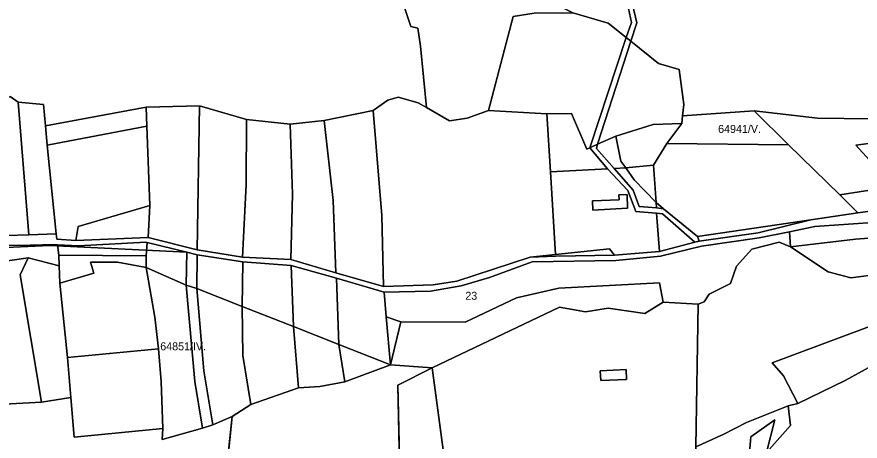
# Model space of a CAD drawing. Extents: x -521261 to -517465, y -1182764 to -1179456.
# Drawn here: x -520761 to -520234, y -1181154 to -1180889 of the extents above; entities that cross this region are included whole.
import ezdxf

# ---------------------------------------------------------------- set-up
doc = ezdxf.new("R2010")
doc.units = 0
for name, color, linetype in [('95610013', 7, 'Continuous'), ('95620013', 7, 'Continuous'), ('95640013', 7, 'Continuous'), ('95660013', 7, 'Continuous')]:
    doc.layers.add(name, color=color, linetype=linetype)

msp = doc.modelspace()

# ---------------------------------------------------------------- linework, layer by layer
at = {"layer": '95610013'}
for points in [[(-520413.63, -1180886.67), (-520391.57, -1180893.1), (-520380.19, -1180902.05), (-520402.93, -1180971), (-520404.76, -1180971.74), (-520414.45, -1180949.49), (-520429.91, -1180949.77), (-520466.27, -1180947.66), (-520450.85, -1180888.84), (-520437.74, -1180886.84)], [(-520377.28, -1180904.27), (-520360, -1180918.29), (-520347.18, -1180922.08), (-520344.3, -1180943.96), (-520344.99, -1180950.96), (-520345.48, -1180955.74), (-520363.32, -1180956.31), (-520386.65, -1180963.6), (-520398.19, -1180968.76)], [(-520765.33, -1180938.81), (-520760.21, -1180942.51), (-520753.55, -1181025.36), (-520781.8, -1181026.11), (-520776.76, -1181017.76), (-520775.73, -1181015.12), (-520782.22, -1180993.52), (-520780.05, -1180973.32), (-520778.12, -1180965.89), (-520770.41, -1180941.78)], [(-520522.77, -1180939.3), (-520510.22, -1180942.87), (-520505.09, -1180945.85), (-520490.67, -1180954.03), (-520479.73, -1180952.5), (-520466.27, -1180947.66), (-520429.91, -1180949.77), (-520427.6, -1180986), (-520424.35, -1181037.58), (-520440.29, -1181039.26), (-520486.21, -1181054.21), (-520500.85, -1181056.65), (-520531.99, -1181057.53), (-520532.9, -1181013.34), (-520538.35, -1180947.59), (-520529.26, -1180941.13)], [(-520744.49, -1180944), (-520743.19, -1180957.3), (-520742.11, -1180969.27), (-520736.5, -1181024.64), (-520753.55, -1181025.36), (-520760.21, -1180942.51)], [(-520646.99, -1180944.71), (-520648.3, -1181034.75), (-520679.07, -1181027.05), (-520678, -1181007.02), (-520679.88, -1180957.43), (-520680.17, -1180945.51)], [(-520617.63, -1180953.24), (-520617.73, -1180993.81), (-520619.96, -1181039.3), (-520648.3, -1181034.75), (-520646.99, -1180944.71)], [(-520538.35, -1180947.59), (-520532.9, -1181013.34), (-520531.99, -1181057.53), (-520561.77, -1181049.02), (-520563.49, -1181003.85), (-520569.05, -1180953.85)], [(-520414.45, -1180949.49), (-520404.76, -1180971.74), (-520402.93, -1180971), (-520391.92, -1180984.05), (-520427.6, -1180986), (-520429.91, -1180949.77)], [(-520300.29, -1180947.88), (-520278.88, -1180969.13), (-520354.95, -1180968.17), (-520345.48, -1180955.74), (-520344.99, -1180950.96)], [(-520260.64, -1180952.48), (-520227.61, -1180952.85), (-520219.04, -1180948.87), (-520200.55, -1180964.48), (-520236.79, -1180969.29), (-520213.15, -1180995.05), (-520246.78, -1181000.33), (-520278.88, -1180969.13), (-520300.29, -1180947.88)], [(-520212.94, -1180946.42), (-520201.71, -1180960.23), (-520187.3, -1180962.26), (-520183.85, -1180959.97), (-520160.25, -1180989.16), (-520140.01, -1181013.64), (-520196.24, -1181010.47), (-520209.39, -1181007.96), (-520235.48, -1181011.57), (-520246.78, -1181000.33), (-520213.15, -1180995.05), (-520236.79, -1180969.29), (-520200.55, -1180964.48), (-520219.04, -1180948.87)], [(-520590.31, -1180956.29), (-520588.89, -1180999.87), (-520589.94, -1181040.83), (-520619.96, -1181039.3), (-520617.73, -1180993.81), (-520617.63, -1180953.24)], [(-520569.05, -1180953.85), (-520563.49, -1181003.85), (-520561.77, -1181049.02), (-520589.94, -1181040.83), (-520588.89, -1180999.87), (-520590.31, -1180956.29)], [(-520363.32, -1180956.31), (-520345.48, -1180955.74), (-520354.95, -1180968.17), (-520363.12, -1180981.91), (-520380.53, -1180983.43), (-520383.57, -1180979.21), (-520386.65, -1180963.6)], [(-520742.11, -1180969.27), (-520679.88, -1180957.43), (-520678, -1181007.02), (-520722.82, -1181020.21), (-520724.29, -1181028.9), (-520736.16, -1181028.06), (-520736.5, -1181024.64)], [(-520398.19, -1180968.76), (-520386.65, -1180963.6), (-520383.57, -1180979.21), (-520380.53, -1180983.43), (-520387.73, -1180983.85), (-520398.77, -1180971.41)], [(-520354.95, -1180968.17), (-520278.88, -1180969.13), (-520246.78, -1181000.33), (-520235.48, -1181011.57), (-520264.93, -1181015.96), (-520335.73, -1181026.42), (-520356.95, -1181009.05), (-520361.63, -1181005.12), (-520363.12, -1180981.91)], [(-520678, -1181007.02), (-520679.07, -1181027.05), (-520724.29, -1181028.9), (-520722.82, -1181020.21)], [(-520361.32, -1181008.5), (-520361.63, -1181005.12), (-520356.95, -1181009.05)], [(-520361.22, -1181011.78), (-520357.66, -1181012.23), (-520337.45, -1181029.91), (-520359.36, -1181035.81)], [(-520390.73, -1181034.03), (-520387.65, -1181038.15), (-520424.28, -1181038.64), (-520440.29, -1181039.26), (-520424.35, -1181037.58)], [(-520754, -1181039.73), (-520758.98, -1181050.37), (-520745.59, -1181130), (-520769.1, -1181131.19), (-520787.16, -1181111.94), (-520795.31, -1181089.15), (-520789.59, -1181054.58), (-520789.95, -1181044.99)], [(-520734.68, -1181044.73), (-520734.18, -1181055.46), (-520729.43, -1181102.02), (-520727.31, -1181126.94), (-520745.59, -1181130), (-520758.98, -1181050.37), (-520754, -1181039.73)], [(-520715.02, -1181042.38), (-520698.14, -1181042.43), (-520680.34, -1181045.76), (-520674.82, -1181076.71), (-520672.52, -1181096.48), (-520729.43, -1181102.02), (-520734.18, -1181055.46), (-520712.92, -1181049.21)], [(-520655.3, -1181056.85), (-520649.82, -1181117.07), (-520645.15, -1181146.15), (-520670.21, -1181153.14), (-520669.91, -1181146.41), (-520670.9, -1181116.98), (-520672.52, -1181096.48), (-520674.82, -1181076.71), (-520680.34, -1181045.76)], [(-520655.3, -1181056.85), (-520648.69, -1181058.96), (-520644.18, -1181110.25), (-520638.52, -1181144.14), (-520645.15, -1181146.15), (-520649.82, -1181117.07)], [(-520620.31, -1181070.08), (-520619.94, -1181100.8), (-520614.85, -1181131.39), (-520626.5, -1181138.86), (-520638.52, -1181144.14), (-520644.18, -1181110.25), (-520648.69, -1181058.96)], [(-520588.28, -1181082.68), (-520585.05, -1181120.87), (-520614.85, -1181131.39), (-520619.94, -1181100.8), (-520620.31, -1181070.08)], [(-520559.83, -1181093.86), (-520556.17, -1181117.12), (-520571.69, -1181120.15), (-520585.05, -1181120.87), (-520588.28, -1181082.68)], [(-520729.43, -1181102.02), (-520672.52, -1181096.48), (-520670.9, -1181116.98), (-520669.91, -1181146.41), (-520725.36, -1181151.77), (-520727.31, -1181126.94)], [(-520527.54, -1181106.61), (-520556.17, -1181117.12), (-520559.83, -1181093.86)], [(-520501.61, -1181108.38), (-520522.92, -1181119.2), (-520521.72, -1181178.92), (-520635.15, -1181227.75), (-520634.86, -1181222.95), (-520634.84, -1181222.55), (-520632.77, -1181200.01), (-520629.67, -1181169.79), (-520626.5, -1181138.86), (-520614.85, -1181131.39), (-520585.05, -1181120.87), (-520571.69, -1181120.15), (-520556.17, -1181117.12), (-520527.54, -1181106.61)]]:
    msp.add_lwpolyline(points, close=True, dxfattribs=at)
at = {"layer": '95620013'}
for points in [[(-520153.4, -1180806.35), (-520157.92, -1180932.93), (-520196.52, -1180926.36), (-520199.57, -1180927.79), (-520202.96, -1180943.49), (-520212.94, -1180946.42), (-520219.04, -1180948.87), (-520227.61, -1180952.85), (-520260.64, -1180952.48), (-520300.29, -1180947.88), (-520344.99, -1180950.96), (-520344.3, -1180943.96), (-520347.18, -1180922.08), (-520360, -1180918.29), (-520377.28, -1180904.27), (-520373.63, -1180892.94), (-520376.27, -1180881.41), (-520440.58, -1180853.57), (-520296.21, -1180829.93)], [(-520447.63, -1180855.08), (-520441.44, -1180872.23), (-520413.63, -1180886.67), (-520437.74, -1180886.84), (-520450.85, -1180888.84), (-520466.27, -1180947.66), (-520479.73, -1180952.5), (-520490.67, -1180954.03), (-520505.09, -1180945.85), (-520508.85, -1180907.38), (-520510.51, -1180896.3), (-520514.96, -1180895.18), (-520522.73, -1180871.37), (-520521.14, -1180864.38), (-520485.24, -1180860)], [(-520441.44, -1180872.23), (-520447.63, -1180855.08), (-520378.72, -1180883.92), (-520376.96, -1180892.63), (-520380.19, -1180902.05), (-520391.57, -1180893.1), (-520413.63, -1180886.67)], [(-520297.08, -1181027.2), (-520278.14, -1181023.43), (-520277.6, -1181032.76), (-520284.69, -1181029.91), (-520301.71, -1181034.37), (-520311.25, -1181044.99), (-520315.05, -1181055.77), (-520328.37, -1181062.33), (-520331.46, -1181067.2), (-520335.2, -1181068.61), (-520357.23, -1181067.33), (-520359.55, -1181055.32), (-520422.46, -1181058.72), (-520448.82, -1181064.74), (-520480.94, -1181079.95), (-520521.06, -1181079.73), (-520530.28, -1181076.6), (-520531.56, -1181061.16), (-520502.66, -1181060.46), (-520483.49, -1181057.27), (-520465.6, -1181051.94), (-520439.04, -1181042.18), (-520386.77, -1181041.34), (-520358.9, -1181038.71), (-520333.23, -1181032.5)], [(-520654.8, -1181036.24), (-520648.35, -1181037.93), (-520648.69, -1181058.96), (-520655.3, -1181056.85)], [(-520648.35, -1181037.93), (-520619.95, -1181042.28), (-520620.31, -1181070.08), (-520648.69, -1181058.96)], [(-520619.95, -1181042.28), (-520589.61, -1181044.45), (-520588.28, -1181082.68), (-520620.31, -1181070.08)], [(-520589.61, -1181044.45), (-520561.25, -1181052.52), (-520559.83, -1181093.86), (-520588.28, -1181082.68)], [(-520531.56, -1181061.16), (-520530.28, -1181076.6), (-520527.54, -1181106.61), (-520559.83, -1181093.86), (-520561.25, -1181052.52)], [(-520422.46, -1181058.72), (-520359.55, -1181055.32), (-520357.23, -1181067.33), (-520368.56, -1181074.46), (-520391.51, -1181071.12), (-520405.61, -1181073.38), (-520422.02, -1181070.48), (-520501.61, -1181108.38), (-520527.54, -1181106.61), (-520521.06, -1181079.73), (-520480.94, -1181079.95), (-520448.82, -1181064.74)], [(-520530.28, -1181076.6), (-520521.06, -1181079.73), (-520527.54, -1181106.61)], [(-520522.92, -1181119.2), (-520501.61, -1181108.38), (-520493.92, -1181165.95), (-520521.72, -1181178.92)]]:
    msp.add_lwpolyline(points, close=True, dxfattribs=at)
for points in [[(-520522.73, -1180871.37), (-520514.96, -1180895.18), (-520510.51, -1180896.3), (-520508.85, -1180907.38), (-520505.09, -1180945.85), (-520510.22, -1180942.87), (-520522.77, -1180939.3), (-520529.26, -1180941.13), (-520538.35, -1180947.59), (-520569.05, -1180953.85), (-520590.31, -1180956.29), (-520617.63, -1180953.24), (-520646.99, -1180944.71), (-520680.17, -1180945.51), (-520743.19, -1180957.3), (-520744.49, -1180944), (-520760.21, -1180942.51), (-520765.33, -1180938.81)], [(-520769.1, -1181131.19), (-520745.59, -1181130), (-520727.31, -1181126.94), (-520725.36, -1181151.77), (-520669.91, -1181146.41), (-520670.21, -1181153.14), (-520645.15, -1181146.15), (-520638.52, -1181144.14), (-520626.5, -1181138.86), (-520629.67, -1181169.79), (-520706.63, -1181195.17), (-520741.92, -1181221.6), (-520743.69, -1181236.73), (-520746.87, -1181263.8), (-520750.08, -1181291.23), (-520752.71, -1181313.69), (-520748.34, -1181330.19), (-520743.26, -1181349.41), (-520738.26, -1181368.28), (-520732.6, -1181389.64), (-520725.79, -1181415.51), (-520718.89, -1181441.47), (-520723.52, -1181473.69), (-520728.04, -1181505.07)]]:
    msp.add_lwpolyline(points, dxfattribs=at)
at = {"layer": '95640013'}
for points in [[(-520447.63, -1180855.08), (-520440.58, -1180853.57), (-520376.27, -1180881.41), (-520373.63, -1180892.94), (-520377.28, -1180904.27), (-520380.19, -1180902.05), (-520376.96, -1180892.63), (-520378.72, -1180883.92)], [(-520377.28, -1180904.27), (-520398.19, -1180968.76), (-520402.93, -1180971), (-520380.19, -1180902.05)], [(-520680.17, -1180945.51), (-520679.88, -1180957.43), (-520742.11, -1180969.27), (-520743.19, -1180957.3)], [(-520398.19, -1180968.76), (-520398.77, -1180971.41), (-520387.73, -1180983.85), (-520375.85, -1180997.36), (-520372.13, -1181007.57), (-520361.32, -1181008.5), (-520356.95, -1181009.05), (-520335.73, -1181026.42), (-520334.59, -1181029.23), (-520337.45, -1181029.91), (-520357.66, -1181012.23), (-520361.22, -1181011.78), (-520374.15, -1181010.71), (-520379.29, -1180997.62), (-520391.92, -1180984.05), (-520402.93, -1180971)], [(-520380.53, -1180983.43), (-520363.12, -1180981.91), (-520361.63, -1181005.12), (-520375.3, -1180990.97)], [(-520427.6, -1180986), (-520391.92, -1180984.05), (-520379.29, -1180997.62), (-520374.15, -1181010.71), (-520361.22, -1181011.78), (-520359.36, -1181035.81), (-520387.65, -1181038.15), (-520390.73, -1181034.03), (-520424.35, -1181037.58)], [(-520387.73, -1180983.85), (-520380.53, -1180983.43), (-520375.3, -1180990.97), (-520361.63, -1181005.12), (-520361.32, -1181008.5), (-520372.13, -1181007.57), (-520375.85, -1180997.36)], [(-520379.68, -1181000.23), (-520379.39, -1181008.65), (-520401.05, -1181009.9), (-520401.4, -1181004.03), (-520384.66, -1181003.43), (-520384.81, -1181000.42)], [(-520379.68, -1181000.23), (-520384.81, -1181000.42), (-520384.66, -1181003.43), (-520401.4, -1181004.03), (-520401.05, -1181009.9), (-520379.39, -1181008.65)], [(-520264.93, -1181015.96), (-520297.78, -1181024.07), (-520334.59, -1181029.23), (-520335.73, -1181026.42)], [(-520161.81, -1181016.06), (-520131.4, -1181022.11), (-520113.26, -1181023.55), (-520083.95, -1181020.65), (-520070.28, -1181022.36), (-520056.82, -1181033.22), (-520048.82, -1181038.46), (-520068.56, -1181044.19), (-520110.95, -1181047.78), (-520220.57, -1181049.61), (-520239.97, -1181052.18), (-520253.94, -1181048.36), (-520277.6, -1181032.76), (-520278.14, -1181023.43), (-520262.27, -1181020.23), (-520202.17, -1181016.05)], [(-520737.28, -1181031.47), (-520735.59, -1181031.57), (-520734.93, -1181038.06), (-520734.68, -1181044.73), (-520754, -1181039.73), (-520789.95, -1181044.99), (-520789.78, -1181039.28), (-520784.95, -1181032.19), (-520752.89, -1181031.72)], [(-520680.51, -1181030), (-520679.65, -1181030.21), (-520680.34, -1181038.45), (-520734.93, -1181038.06), (-520735.59, -1181031.57), (-520722.56, -1181032.13)], [(-520679.65, -1181030.21), (-520654.8, -1181036.24), (-520655.3, -1181056.85), (-520680.34, -1181045.76), (-520680.34, -1181038.45)], [(-520277.6, -1181032.76), (-520253.94, -1181048.36), (-520239.97, -1181052.18), (-520220.57, -1181049.61), (-520214.23, -1181077.46), (-520289.13, -1181105.34), (-520281.95, -1181113.37), (-520272.96, -1181130.65), (-520279.13, -1181132.17), (-520305.16, -1181142.6), (-520319.71, -1181150.12), (-520336.76, -1181157.91), (-520335.2, -1181068.61), (-520331.46, -1181067.2), (-520328.37, -1181062.33), (-520315.05, -1181055.77), (-520311.25, -1181044.99), (-520301.71, -1181034.37), (-520284.69, -1181029.91)], [(-520680.34, -1181038.45), (-520680.34, -1181045.76), (-520698.14, -1181042.43), (-520715.02, -1181042.38), (-520712.92, -1181049.21), (-520734.18, -1181055.46), (-520734.68, -1181044.73), (-520734.93, -1181038.06)], [(-520335.2, -1181068.61), (-520336.76, -1181157.91), (-520337.13, -1181163.47), (-520382.21, -1181160.56), (-520418.54, -1181159.62), (-520460.89, -1181164.03), (-520478.96, -1181172.1), (-520493.39, -1181174.7), (-520493.92, -1181165.95), (-520501.61, -1181108.38), (-520422.02, -1181070.48), (-520405.61, -1181073.38), (-520391.51, -1181071.12), (-520368.56, -1181074.46), (-520357.23, -1181067.33)], [(-520210.11, -1181097.99), (-520243.42, -1181116.34), (-520272.96, -1181130.65), (-520281.95, -1181113.37), (-520289.13, -1181105.34), (-520214.23, -1181077.46)], [(-520208.33, -1181106.65), (-520202.7, -1181126.58), (-520208.38, -1181133.79), (-520200.46, -1181154.03), (-520254.49, -1181176.66), (-520288.03, -1181193.76), (-520297.05, -1181192.49), (-520302.49, -1181183.79), (-520304.08, -1181171.38), (-520302.27, -1181151.64), (-520287.43, -1181140.94), (-520292.51, -1181161.26), (-520277.55, -1181144.55), (-520279.13, -1181132.17), (-520272.96, -1181130.65), (-520243.42, -1181116.34), (-520210.11, -1181097.99)], [(-520380.32, -1181109.5), (-520396.45, -1181110.24), (-520396.16, -1181116.38), (-520380.02, -1181115.64)], [(-520380.32, -1181109.5), (-520380.02, -1181115.64), (-520396.16, -1181116.38), (-520396.45, -1181110.24)], [(-520305.16, -1181142.6), (-520279.13, -1181132.17), (-520277.55, -1181144.55), (-520292.51, -1181161.26), (-520287.43, -1181140.94), (-520302.27, -1181151.64), (-520304.08, -1181171.38), (-520337.13, -1181163.47), (-520336.76, -1181157.91), (-520319.71, -1181150.12)]]:
    msp.add_lwpolyline(points, close=True, dxfattribs=at)
for points in [[(-520781.8, -1181026.11), (-520753.55, -1181025.36), (-520736.5, -1181024.64), (-520736.16, -1181028.06), (-520724.29, -1181028.9), (-520679.07, -1181027.05), (-520648.3, -1181034.75), (-520619.96, -1181039.3), (-520589.94, -1181040.83), (-520561.77, -1181049.02), (-520531.99, -1181057.53), (-520500.85, -1181056.65), (-520486.21, -1181054.21), (-520440.29, -1181039.26), (-520424.28, -1181038.64), (-520387.65, -1181038.15), (-520359.36, -1181035.81), (-520337.45, -1181029.91), (-520334.59, -1181029.23), (-520297.78, -1181024.07), (-520264.93, -1181015.96), (-520235.48, -1181011.57), (-520209.39, -1181007.96)], [(-520202.17, -1181016.05), (-520262.27, -1181020.23), (-520278.14, -1181023.43), (-520297.08, -1181027.2), (-520333.23, -1181032.5), (-520358.9, -1181038.71), (-520386.77, -1181041.34), (-520439.04, -1181042.18), (-520465.6, -1181051.94), (-520483.49, -1181057.27), (-520502.66, -1181060.46), (-520531.56, -1181061.16), (-520561.25, -1181052.52), (-520589.61, -1181044.45), (-520619.95, -1181042.28), (-520648.35, -1181037.93), (-520654.8, -1181036.24), (-520679.65, -1181030.21), (-520680.51, -1181030), (-520722.56, -1181032.13), (-520735.59, -1181031.57), (-520737.28, -1181031.47), (-520752.89, -1181031.72), (-520784.95, -1181032.19)]]:
    msp.add_lwpolyline(points, dxfattribs=at)
at = {"layer": '95660013'}
for points in [[(-520153.4, -1180806.35), (-520157.92, -1180932.93), (-520165.05, -1180947.64), (-520187.42, -1180954.15), (-520203.9, -1180952.83), (-520202.96, -1180943.49), (-520212.94, -1180946.42), (-520219.04, -1180948.87), (-520227.61, -1180952.85), (-520260.64, -1180952.48), (-520300.29, -1180947.88), (-520344.99, -1180950.96), (-520344.3, -1180943.96), (-520347.18, -1180922.08), (-520360, -1180918.29), (-520377.28, -1180904.27), (-520380.19, -1180902.05), (-520391.57, -1180893.1), (-520413.63, -1180886.67)], [(-520413.63, -1180886.67), (-520391.57, -1180893.1), (-520380.19, -1180902.05), (-520377.28, -1180904.27), (-520360, -1180918.29), (-520347.18, -1180922.08), (-520344.3, -1180943.96), (-520344.99, -1180950.96), (-520300.29, -1180947.88), (-520260.64, -1180952.48), (-520227.61, -1180952.85), (-520219.04, -1180948.87), (-520212.94, -1180946.42), (-520202.96, -1180943.49), (-520203.9, -1180952.83), (-520187.42, -1180954.15), (-520165.05, -1180947.64), (-520148.15, -1180951.58), (-520129.83, -1180952.33), (-520109.27, -1180947.28), (-520063.22, -1180921.42), (-520052.08, -1180921.54), (-520055.89, -1180870.36)], [(-520450.85, -1180888.84), (-520466.27, -1180947.66), (-520479.73, -1180952.5), (-520490.67, -1180954.03), (-520505.09, -1180945.85), (-520510.22, -1180942.87), (-520522.77, -1180939.3), (-520529.26, -1180941.13), (-520538.35, -1180947.59), (-520569.05, -1180953.85), (-520590.31, -1180956.29), (-520617.63, -1180953.24), (-520646.99, -1180944.71), (-520680.17, -1180945.51), (-520743.19, -1180957.3), (-520744.49, -1180944), (-520760.21, -1180942.51), (-520765.33, -1180938.81)], [(-520765.33, -1180938.81), (-520760.21, -1180942.51), (-520744.49, -1180944), (-520743.19, -1180957.3), (-520680.17, -1180945.51), (-520646.99, -1180944.71), (-520617.63, -1180953.24), (-520590.31, -1180956.29), (-520569.05, -1180953.85), (-520538.35, -1180947.59), (-520529.26, -1180941.13), (-520522.77, -1180939.3), (-520510.22, -1180942.87), (-520505.09, -1180945.85), (-520490.67, -1180954.03), (-520479.73, -1180952.5), (-520466.27, -1180947.66), (-520450.85, -1180888.84)], [(-520209, -1181026), (-520237, -1181028), (-520277.6, -1181032.76), (-520278.14, -1181023.43), (-520297.08, -1181027.2), (-520333.23, -1181032.5), (-520358.9, -1181038.71), (-520386.77, -1181041.34), (-520439.04, -1181042.18), (-520465.6, -1181051.94), (-520483.49, -1181057.27), (-520502.66, -1181060.46), (-520531.56, -1181061.16), (-520561.25, -1181052.52), (-520589.61, -1181044.45), (-520619.95, -1181042.28), (-520648.35, -1181037.93), (-520654.8, -1181036.24), (-520740.5, -1181032), (-520786.29, -1181034.16)], [(-520493.92, -1181165.95), (-520501.61, -1181108.38), (-520422.02, -1181070.48), (-520405.61, -1181073.38), (-520391.51, -1181071.12), (-520368.56, -1181074.46), (-520357.23, -1181067.33), (-520335.2, -1181068.61), (-520331.46, -1181067.2), (-520328.37, -1181062.33), (-520315.05, -1181055.77), (-520311.25, -1181044.99), (-520301.71, -1181034.37), (-520284.69, -1181029.91), (-520277.6, -1181032.76), (-520237, -1181028), (-520209, -1181026)], [(-520786.29, -1181034.16), (-520740.5, -1181032), (-520654.8, -1181036.24), (-520655.3, -1181056.85), (-520648.69, -1181058.96), (-520620.31, -1181070.08), (-520588.28, -1181082.68), (-520559.83, -1181093.86), (-520527.54, -1181106.61), (-520501.61, -1181108.38), (-520522.92, -1181119.2), (-520522.19, -1181155.36)], [(-520522.19, -1181155.36), (-520522.92, -1181119.2), (-520501.61, -1181108.38), (-520493.92, -1181165.95)], [(-520769.1, -1181131.19), (-520745.59, -1181130), (-520727.31, -1181126.94), (-520725.36, -1181151.77), (-520669.91, -1181146.41), (-520670.21, -1181153.14), (-520645.15, -1181146.15), (-520638.52, -1181144.14), (-520626.5, -1181138.86), (-520628.5, -1181158.39)], [(-520628.5, -1181158.39), (-520626.5, -1181138.86), (-520638.52, -1181144.14), (-520645.15, -1181146.15), (-520670.21, -1181153.14), (-520669.91, -1181146.41), (-520725.36, -1181151.77), (-520727.31, -1181126.94), (-520745.59, -1181130), (-520769.1, -1181131.19)]]:
    msp.add_lwpolyline(points, dxfattribs=at)
msp.add_lwpolyline([(-520278.14, -1181023.43), (-520277.6, -1181032.76), (-520284.69, -1181029.91), (-520301.71, -1181034.37), (-520311.25, -1181044.99), (-520315.05, -1181055.77), (-520328.37, -1181062.33), (-520331.46, -1181067.2), (-520335.2, -1181068.61), (-520357.23, -1181067.33), (-520368.56, -1181074.46), (-520391.51, -1181071.12), (-520405.61, -1181073.38), (-520422.02, -1181070.48), (-520501.61, -1181108.38), (-520527.54, -1181106.61), (-520559.83, -1181093.86), (-520588.28, -1181082.68), (-520620.31, -1181070.08), (-520648.69, -1181058.96), (-520655.3, -1181056.85), (-520654.8, -1181036.24), (-520648.35, -1181037.93), (-520619.95, -1181042.28), (-520589.61, -1181044.45), (-520561.25, -1181052.52), (-520531.56, -1181061.16), (-520502.66, -1181060.46), (-520483.49, -1181057.27), (-520465.6, -1181051.94), (-520439.04, -1181042.18), (-520386.77, -1181041.34), (-520358.9, -1181038.71), (-520333.23, -1181032.5), (-520297.08, -1181027.2)], close=True, dxfattribs=at)

# ---------------------------------------------------------------- texts
for s, rotation, p in [('64941/V.', 0, (-520322.8, -1180961.67)), ('23', 0, (-520480.8, -1181065.91)), ('64851/IV.', 360, (-520671.47, -1181097.5))]:
    msp.add_text(s, height=5, rotation=rotation, dxfattribs=at).set_placement(p)

doc.saveas('drawing.dxf')
